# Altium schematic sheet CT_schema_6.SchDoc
size 251 x 159 mm
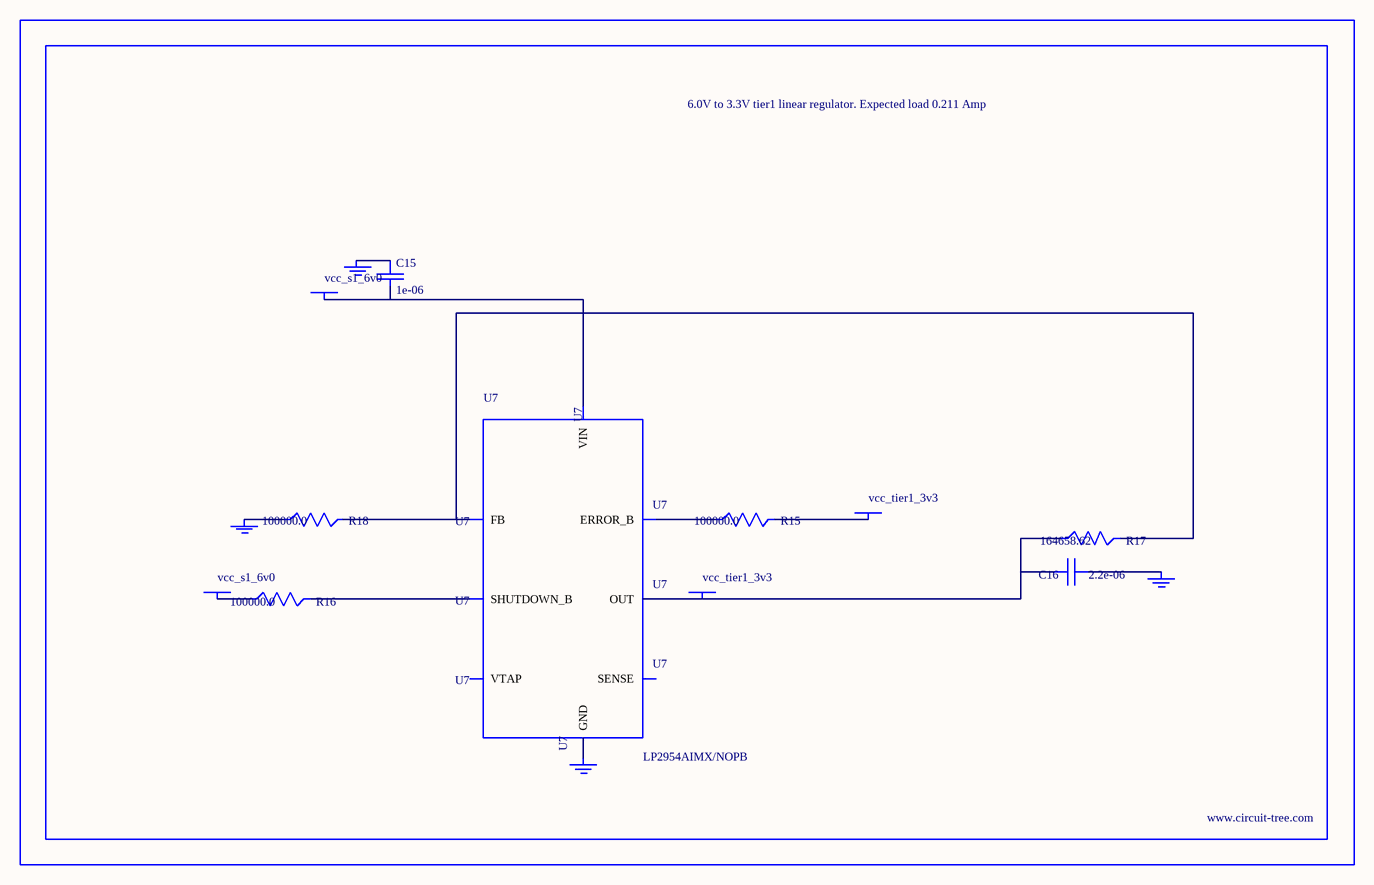
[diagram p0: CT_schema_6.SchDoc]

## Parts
BORDER5  (no value)
C15  1e-06  [EXV-9B]
C16  2.2e-06  [EXV-9B]
GND_INSTANCE_5_0  (no value)
GND_INSTANCE_5_1  (no value)
GND_INSTANCE_5_2  (no value)
GND_INSTANCE_5_3  (no value)
POWER_INSTANCE_5_0  vcc_s1_6v0
POWER_INSTANCE_5_1  vcc_tier1_3v3
POWER_INSTANCE_5_2  vcc_s1_6v0
POWER_INSTANCE_5_3  vcc_tier1_3v3
R15  100000.0  [R0603]
R16  100000.0  [R0603]
R17  164658.62  [R0603]
R18  100000.0  [R0603]
U7  LP2954AIMX/NOPB  [LP2954]

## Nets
NetC15_1: C15.1 GND_INSTANCE_5_2.0(GND)
NetC15_2: C15.2 POWER_INSTANCE_5_2.0(PWR) U7.8(VIN)
NetC16_1: C16.1 GND_INSTANCE_5_0.0(GND)
NetC16_2: C16.2 POWER_INSTANCE_5_3.0(PWR) R17.1 U7.1(OUT)
NetGND_INSTANCE_5_1_0: GND_INSTANCE_5_1.0(GND) R18.1
NetGND_INSTANCE_5_3_0: GND_INSTANCE_5_3.0(GND) U7.4(GND)
NetPOWER_INSTANCE_5_0_0: POWER_INSTANCE_5_0.0(PWR) R16.1
NetPOWER_INSTANCE_5_1_0: POWER_INSTANCE_5_1.0(PWR) R15.2
NetR15_1: R15.1 U7.5(ERROR_B)
NetR16_2: R16.2 U7.3(SHUTDOWN_B)
NetR17_2: R17.2 R18.2 U7.7(FB)

Not connected (* = marked no-connect by the designer): U7 2(SENSE) 6(VTAP)

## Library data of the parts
BORDER5 = BORDER_PAGE5
C15 = EDK105M050A9BAA
C16 = EDK225M050A9BAA
GND_INSTANCE_5_0-GND_INSTANCE_5_3 = GND
POWER_INSTANCE_5_0-POWER_INSTANCE_5_3 = PWR
R15 R16 R18 = RC0603JR-07100KL
R17 = R17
